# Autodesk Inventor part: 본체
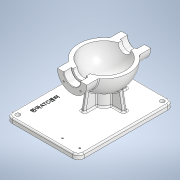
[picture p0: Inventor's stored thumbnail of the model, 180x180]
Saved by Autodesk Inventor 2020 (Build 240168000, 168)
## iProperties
Created: 2015-12
Part Number: 본체
Material: 알루미늄 6061
Document SubType Name: Modeling
Designer: mduedu
Density: 2.71 g/cm^3
Mass: 1330.63 g
Surface Area: 1128.56 cm^2
Volume: 491.008 cm^3
Appearance: 알루미늄 - 평지
Author: mduedu
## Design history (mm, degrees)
sketch "스케치1"
  geometry: L1 (-53, 0)-(53, 0); A1 r 53 centre (0, 0) between (53, 0) and (-53, 0); 2 further points
  constraints: 2 coincident, 2 end point, 2 point on circle, 1 centre point, 1 horizontal, 1 midpoint
  dimensions: "d0" = 53 radius of A1
revolve "회전1" sketch "스케치1" stored, may be unused: angle "d2" = 90 deg
feature "쉘1" dims "d11" = 8
node "작업 평면1"
sketch "스케치2"
  geometry: C1 r 31 at (0, 0); 1 further point
  constraints: 1 centre point, 1 coincident
  dimensions: "d4" = 62 diameter of C1
extrude "돌출1" join sketch "스케치2" stored distance "d5" = 10; taper "d6" = 0 deg
hole "구멍1" diameter "d14" = 35; stored, may be unused: countersink angle "d18" = 90 deg, drill point angle "d20" = 0 deg; dims "d12" = 10, "d13" = 10, "d15" = 6, "d16" = 4, "d17" = 2, "d19" = 16
hole "구멍2" diameter "d23" = 27; stored, may be unused: countersink angle "d27" = 90 deg, drill point angle "d29" = 0 deg; dims "d21" = 10, "d22" = 10, "d24" = 6, "d25" = 4, "d26" = 2, "d28" = 16
fillet "모깎기1" dims "d30" = 0.3
chamfer "모따기1" distance "d40" = 1; stored, may be unused: second distance "d41" = 2, angle "d42" = 45 deg
sketch "스케치4"
  geometry: L1 (0, 0)-(0, -25); L2 (0, 0)-(-17.678, -17.678); A1 r 25 centre (0, 0) between (-17.678, -17.678) and (0, -25); 1 further point
  constraints: 4 end point, 2 point on circle, 1 centre point, 1 coincident, 1 vertical
  dimensions: "d43" = 50 diameter of A1; "d47" = 45 deg angle of L1 L2
hole "구멍4" sketch "스케치4" at (-17.678, -17.678) diameter "d49" = 3.242; stored, may be unused: countersink angle "d53" = 90 deg, drill point angle "d55" = 118 deg; dims "d50" = 11, "d51" = 4, "d52" = 2, "d54" = 13
node "작업 평면3"
sketch "스케치6"
  geometry: L1 (-70, -75)-(130, -75); L2 (130, -75)-(130, 76); L3 (130, 76)-(-70, 76); L4 (-70, 76)-(-70, -75); 2 further points
  constraints: 8 end point, 2 parallel, 1 coincident, 1 horizontal, 1 perpendicular
  dimensions: "d158" = 200 distance of L3.end L2.end; "d159" = 151 distance of L2.end L1.end; "d162" = 75 distance from line of L1 point (0, 0); "d163" = 70 distance from line of L4 point (0, 0)
extrude "돌출3" join sketch "스케치6" distance "d80" = 10; taper "d81" = 0 deg
sketch "스케치7"
  geometry: C1 r 20 at (0, 0); 2 further points
  constraints: 2 coincident, 1 centre point
  dimensions: "d82" = 40 diameter of C1
extrude "돌출4" join sketch "스케치7" stored distance "d84" = 10; taper "d85" = 0 deg
sketch "스케치8"
  geometry: 3 further points
  constraints: 2 coincident
hole "구멍6" sketch "스케치8" at (0, 0) diameter "d86" = 20; stored, may be unused: countersink angle "d90" = 90 deg, drill point angle "d92" = 118 deg; dims "d87" = 7, "d88" = 40, "d89" = 5, "d91" = 10
fillet "모깎기2" dims "d93" = 0.3
sketch "스케치9"
  geometry: L1 (-45, -75)-(-38.245, -36.692); L2 (70, -75)-(-130, -75) reference; A1 r 53 centre (0, 0) between (42.988, 31) and (42.988, -31) reference; 1 further point
  constraints: 2 end point, 1 coincident, 1 point on circle, 1 point on line
  dimensions: "d94" = 45 horizontal distance of L1.start point (0, 0); "d160" = 80 deg angle of L2 L1
feature "리브1" sketch "스케치9" dims "d96" = 1, "d97" = 8, "d98" = 0, "d99" = 0, "d100" = 1, "d101" = 1
fillet "모깎기3" dims "d120" = 3
fillet "모깎기4" dims "d121" = 3, "d122" = 3
fillet "모깎기5" dims "d123" = 3
sketch "스케치12"
  geometry: L1 (0, 100)-(0, -100); L2 (0, 100)-(100, 100); L3 (100, 100)-(100, -100); L4 (100, -100)-(0, -100); 2 further points
  constraints: 8 end point, 3 perpendicular, 1 coincident, 1 midpoint, 1 vertical
  dimensions: "d127" = 200 distance of L2.end L3.end; "d129" = 100 distance between parallel lines of L1 L3
extrude "돌출5" cut sketch "스케치12" extent not by distance; stored distance "d130" = 10; taper "d131" = 0 deg
fillet "모깎기10" dims "d164" = 12
fillet "모깎기11" dims "d165" = 3
sketch "스케치15"
  geometry: C1 r 4.5 at (-118, 63); C2 r 4.5 at (58, 63); C3 r 4.5 at (58, -64); A1 r 12 centre (-118, 63) between (-118, 75) and (-130, 63) reference; A2 r 12 centre (58, 63) between (70, 63) and (58, 75) reference; A3 r 12 centre (58, -64) between (58, -76) and (70, -64) reference; 1 further point
  constraints: 3 centre point, 3 coincident, 2 equal radius
  dimensions: "d166" = 9 diameter of C1
extrude "돌출8" cut sketch "스케치15" extent not by distance; stored distance "d167" = 10; taper "d168" = 0 deg
sketch "스케치16"
  geometry: L1 (-130, 63)-(-130, -64) reference; L2 (-118, -76)-(58, -76) reference; 2 further points
  constraints: 1 other
  dimensions: "d169" = 60 distance from line of point (-70, 54) L1; "d170" = 130 distance from line of point (-70, 54) L2
feature "엠보싱2" sketch "스케치16" dims "d171" = 0.5, "d172" = 0
sketch "스케치17"
  geometry: L1 (-118, 76)-(58, 76) reference; L2 (-130, -63)-(-130, 64) reference; 2 further points
  constraints: 1 vertical alignment
  dimensions: "d180" = 13 distance from line of L1 point (-114, 63); "d181" = 16 distance from line of point (-114, 63) L2; "d182" = 36 distance of point (-114, 27) point (-114, 63)
hole "구멍9" sketch "스케치17" at (-114, 63), (-114, 27) diameter "d173" = 3.242; stored, may be unused: countersink angle "d177" = 90 deg, drill point angle "d179" = 0 deg; dims "d174" = 6, "d175" = 4, "d176" = 2, "d178" = 8
node "솔리드1"
mirror "대칭1"
mirror "대칭2"
pattern_circular "원형 패턴1" dims angle "d57" = 360 deg
mirror "대칭3"
pattern_circular "원형 패턴3" dims angle "d103" = 360 deg
other parameters: "d3" = 67, "d77" = -85
